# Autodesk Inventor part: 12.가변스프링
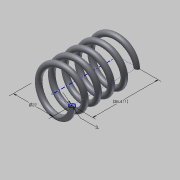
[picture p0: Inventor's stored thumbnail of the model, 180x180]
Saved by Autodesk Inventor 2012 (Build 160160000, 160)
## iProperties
Created: 2014-12
Part Number: 12.가변스프링
Material: 탄소강
Document SubType Name: Modeling
Designer: HOME
Density: 7.87 g/cm^3
Mass: 18.8881 g
Surface Area: 32.5447 cm^2
Volume: 2.40001 cm^3
Author: HOME
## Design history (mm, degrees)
sketch "스케치1"
  geometry: L1 (0, 0)-(11, 0); L2 (11, 0)-(11, 36.411); L3 (11, 36.411)-(0, 36.411); L4 (0, 36.411)-(0, 0); C1 r 1.5 at (11, 0); 1 further point
  constraints: 8 end point, 2 coincident, 2 parallel, 1 centre point, 1 horizontal, 1 perpendicular
  dimensions: "d0" = 22 diameter of L2 L4; "d1" = 36.4112 distance of L1.end L2.end (derived); "d2" = 3 diameter of C1
feature "코일1" pitch "d3" = 10; turns "d5" = 5; dims "d4" = 36.4112 (= d1), "d6" = 0, angle "d7" = 90 deg, angle "d8" = 90 deg, "d9" = 0, "d10" = 0
sketch "스케치2"
  geometry: L1 (-12.5, 0)-(-9.5, 0) reference; 1 further point
  constraints: 1 horizontal alignment
extrude "돌출1" cut sketch "스케치2" stored distance "d11" = 10; taper "d12" = 0 deg
node "작업 평면1"
sketch "스케치3"
  geometry: L1 (-9.5, 0)-(-12.5, 0) reference; 1 further point
  constraints: 1 horizontal alignment
extrude "돌출2" cut sketch "스케치3" stored distance "d13" = 10; taper "d14" = 0 deg
node "솔리드1"
node "절단 모서리 투영1"
node "절단 모서리 투영2"
